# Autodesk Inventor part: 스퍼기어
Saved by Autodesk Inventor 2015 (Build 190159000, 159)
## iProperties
Created: 2025-11
Part Number: 스퍼기어
Material: 일반
Document SubType Name: Modeling
Designer: user
Density: 1 g/cm^3
Appearance: 기본값
Author: user
Author: jhkim
Creation Date: 2025-10-31
Sending System: Autodesk Inventor 2026
Preprocessor: ST-DEVELOPER v20.1
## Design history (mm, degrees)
node "스퍼기어1"
node "솔리드1"
node "기준1"
